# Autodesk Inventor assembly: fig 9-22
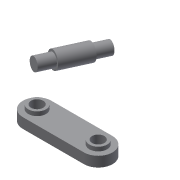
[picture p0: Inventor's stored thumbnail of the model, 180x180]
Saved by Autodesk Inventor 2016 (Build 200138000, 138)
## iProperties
Shininess: 64.0
Length Units: 11269
Angle Units: 11279
Time Units: 11290
Mass Units: 11283
Length Display Precision: 3
Angle Display Precision: 2
Created: 2002-01
Part Number: fig 9-22
Document SubType Name: Assembly
Designer: ***
Density: 0.0
Volumn: 0.0
Area: 0.0
PropertySet Name: Model Information
Control State: 0
Master: False
Checked Out: False
Author: ***
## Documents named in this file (3)
- D:\KAVITA\Autodesk Inventor_ 2016 Project_Kavita\Inventor_Part Files\Inventor_2016_Part\c09_Inv_2016\c09_inv_2016_prt\fig 9-22.iam
- D:\KAVITA\Autodesk Inventor_ 2016 Project_Kavita\Inventor_Part Files\Inventor_2016_Part\c09_Inv_2016\c09_inv_2016_prt\Part5.ipt
- D:\KAVITA\Autodesk Inventor_ 2016 Project_Kavita\Inventor_Part Files\Inventor_2016_Part\c09_Inv_2016\c09_inv_2016_prt\Part6.ipt
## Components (2 placed, 2 different names)
1. Part5:1
2. Part6:1
